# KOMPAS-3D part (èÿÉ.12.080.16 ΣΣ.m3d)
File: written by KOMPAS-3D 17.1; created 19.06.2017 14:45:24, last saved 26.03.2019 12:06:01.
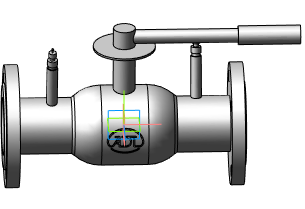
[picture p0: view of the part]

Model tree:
1. Операция без истории:2  (labels: Сталь 20  ГОСТ 1050-88)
